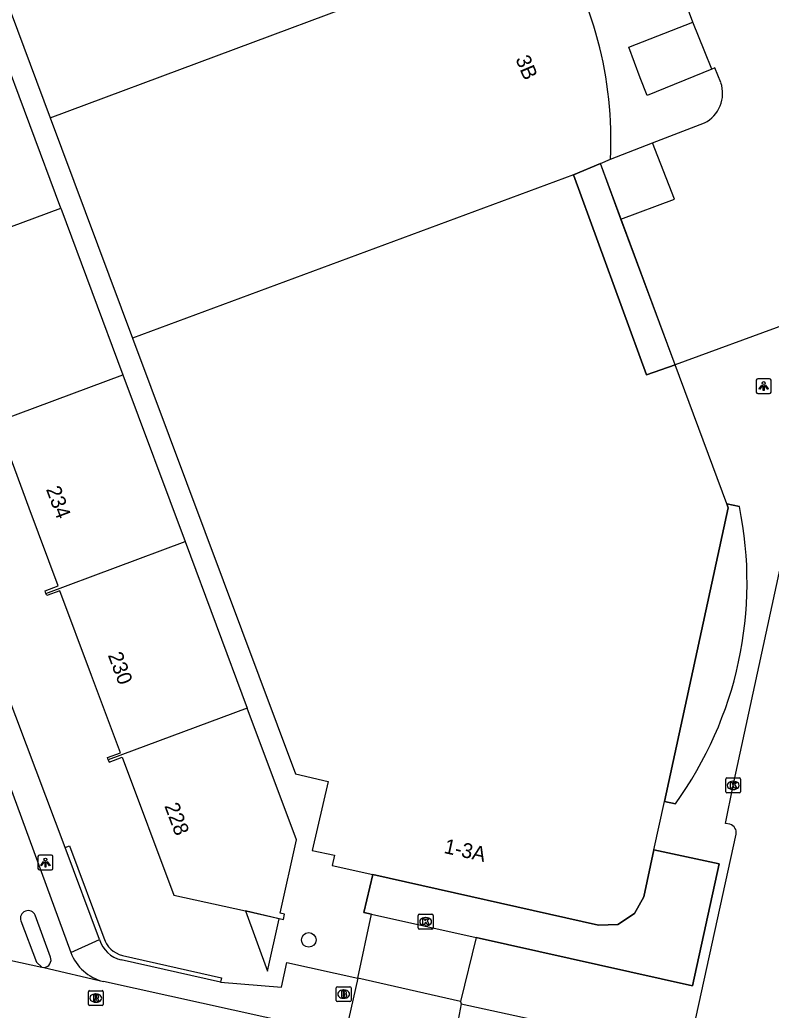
# Model space of a CAD drawing. Extents: x 162172 to 163187, y 382874 to 383684.
# Drawn here: x 162391 to 162441.7, y 383057.9 to 383124.7 of the extents above; entities that cross this region are included whole.
import ezdxf

# ---------------------------------------------------------------- set-up
doc = ezdxf.new("R2010")
doc.units = 0
for name, color, linetype in [('IMGEO_Boom', 7, 'Continuous'), ('IMGEO_Brandkraan', 7, 'Continuous'), ('IMGEO_Fietspad_open', 7, 'Continuous'), ('IMGEO_Kolk', 7, 'Continuous'), ('IMGEO_Lichtpunt', 7, 'Continuous'), ('IMGEO_Muur', 7, 'Continuous'), ('IMGEO_Pand', 7, 'Continuous'), ('IMGEO_Pand_nummerreeks', 7, 'Continuous'), ('IMGEO_Pand_overbouw', 7, 'Continuous'), ('IMGEO_Parkeervlak_open', 7, 'Continuous'), ('IMGEO_Rijbaan_lokaal_open', 7, 'Continuous'), ('IMGEO_Rioolput', 7, 'Continuous'), ('IMGEO_Voetpad_open', 7, 'Continuous')]:
    doc.layers.add(name, color=color, linetype=linetype)

msp = doc.modelspace()

# ---------------------------------------------------------------- linework, layer by layer
at = {"layer": 'IMGEO_Boom'}
msp.add_circle((162410.454, 383062.639), 0.489, dxfattribs=at)
at = {"layer": 'IMGEO_Brandkraan'}
for p, q in [((162412.308, 383058.552), (162412.308, 383059.404)), ((162412.383, 383059.478), (162413.235, 383059.478)), ((162412.796, 383059.258), (162412.821, 383059.258)), ((162413.309, 383059.404), (162413.309, 383058.552)), ((162413.235, 383058.478), (162412.383, 383058.478)), ((162412.819, 383058.698), (162412.794, 383058.698))]:
    msp.add_line(p, q, dxfattribs=at)
for points in [[(162412.308, 383058.552), (162412.308, 383059.404)], [(162412.383, 383059.478), (162413.235, 383059.478)], [(162412.656, 383059.178), (162412.656, 383058.778), (162412.869, 383058.778)], [(162412.887, 383059.178), (162412.656, 383059.178)], [(162412.835, 383059.097), (162412.781, 383059.097), (162412.781, 383059.021)], [(162412.781, 383059.021), (162412.834, 383059.021)], [(162412.843, 383058.945), (162412.781, 383058.945), (162412.781, 383058.864)], [(162413.309, 383059.404), (162413.309, 383058.552)], [(162413.235, 383058.478), (162412.383, 383058.478)], [(162412.781, 383058.864), (162412.843, 383058.864)]]:
    msp.add_lwpolyline(points, dxfattribs=at)
for centre, radius, start, end in [((162412.385, 383059.402), 0.0765, 91.55205, 178.44795), ((162412.385, 383059.402), 0.0765, 91.55205, 178.44795), ((162412.836, 383059.059), 0.0379, 267.82845, 90.93552), ((162412.844, 383058.904), 0.0404, 269.87594, 90.50774), ((162412.891, 383059.033), 0.145, 59.4692, 91.53667), ((162412.916, 383059.08), 0.0922, 285.51372, 58.15012), ((162412.921, 383058.888), 0.105, 301.31148, 78.98903), ((162413.233, 383059.402), 0.0765, 1.55205, 88.44795), ((162413.233, 383059.402), 0.0765, 1.55205, 88.44795), ((162412.385, 383058.554), 0.0765, 181.55205, 268.44795), ((162412.385, 383058.554), 0.0765, 181.55205, 268.44795), ((162412.875, 383059.029), 0.251, 268.66757, 293.53466), ((162413.233, 383058.554), 0.0765, 271.55205, 358.44795), ((162413.233, 383058.554), 0.0765, 271.55205, 358.44795)]:
    msp.add_arc(centre, radius, start, end, dxfattribs=at)
for centre, major_axis, ratio, start_param, end_param in [((162412.795, 383058.978), (-0.387, 0.002), 0.722429, 4.712389, 7.853982), ((162412.82, 383058.978), (-0.39, 0.002), 0.717154, 1.570796, 4.712389)]:
    msp.add_ellipse(centre, major_axis=major_axis, ratio=ratio, start_param=start_param, end_param=end_param, dxfattribs=at)
at = {"layer": 'IMGEO_Fietspad_open'}
for points in [[(162384.643, 383088.38), (162394.394, 383061.785)], [(162393.03, 383061.483), (162391.998, 383064.296)], [(162391.027, 383063.924), (162392.086, 383061.133), (162392.445, 383060.806)]]:
    msp.add_lwpolyline(points, dxfattribs=at)
for centre, radius, start, end in [((162391.518, 383064.094), 0.52, 22.80322, 199.12147), ((162397.377, 383062.933), 3.196, 201.04627, 255.89351), ((162392.553, 383061.291), 0.514, 272.97822, 21.92177)]:
    msp.add_arc(centre, radius, start, end, dxfattribs=at)
at = {"layer": 'IMGEO_Kolk'}
for p, q in [((162438.588, 383072.639), (162438.588, 383073.491)), ((162438.663, 383073.565), (162439.515, 383073.565)), ((162439.076, 383073.345), (162439.101, 383073.345)), ((162439.589, 383073.491), (162439.589, 383072.639)), ((162439.515, 383072.565), (162438.663, 383072.565)), ((162439.099, 383072.785), (162439.074, 383072.785)), ((162417.84, 383063.441), (162417.84, 383064.293)), ((162417.915, 383064.367), (162418.767, 383064.367)), ((162418.841, 383064.293), (162418.841, 383063.441)), ((162418.351, 383063.587), (162418.326, 383063.587)), ((162418.328, 383064.147), (162418.353, 383064.147)), ((162418.767, 383063.367), (162417.915, 383063.367))]:
    msp.add_line(p, q, dxfattribs=at)
for points in [[(162438.588, 383072.639), (162438.588, 383073.491)], [(162438.663, 383073.565), (162439.515, 383073.565)], [(162438.909, 383073.265), (162439.032, 383073.265), (162439.032, 383073.114), (162439.162, 383073.265), (162439.326, 383073.265), (162439.18, 383073.114), (162439.333, 383072.865), (162439.181, 383072.865), (162439.096, 383073.029), (162439.032, 383072.962), (162439.032, 383072.865), (162438.909, 383072.865), (162438.909, 383073.265)], [(162439.589, 383073.491), (162439.589, 383072.639)], [(162439.515, 383072.565), (162438.663, 383072.565)], [(162417.84, 383063.441), (162417.84, 383064.293)], [(162417.915, 383064.367), (162418.767, 383064.367)], [(162418.841, 383064.293), (162418.841, 383063.441)], [(162418.161, 383064.067), (162418.284, 383064.067), (162418.284, 383063.916), (162418.414, 383064.067), (162418.578, 383064.067), (162418.432, 383063.916), (162418.585, 383063.667), (162418.433, 383063.667), (162418.348, 383063.831), (162418.284, 383063.764), (162418.284, 383063.667), (162418.161, 383063.667), (162418.161, 383064.067)], [(162418.767, 383063.367), (162417.915, 383063.367)]]:
    msp.add_lwpolyline(points, dxfattribs=at)
for centre, start, end in [((162438.665, 383073.489), 91.55205, 178.44795), ((162438.665, 383073.489), 91.55205, 178.44795), ((162439.513, 383073.489), 1.55205, 88.44795), ((162439.513, 383073.489), 1.55205, 88.44795), ((162438.665, 383072.641), 181.55205, 268.44795), ((162438.665, 383072.641), 181.55205, 268.44795), ((162439.513, 383072.641), 271.55205, 358.44795), ((162439.513, 383072.641), 271.55205, 358.44795), ((162417.917, 383064.291), 91.55205, 178.44795), ((162417.917, 383064.291), 91.55205, 178.44795), ((162418.765, 383064.291), 1.55205, 88.44795), ((162418.765, 383064.291), 1.55205, 88.44795), ((162417.917, 383063.443), 181.55205, 268.44795), ((162417.917, 383063.443), 181.55205, 268.44795), ((162418.765, 383063.443), 271.55205, 358.44795), ((162418.765, 383063.443), 271.55205, 358.44795)]:
    msp.add_arc(centre, 0.0765, start, end, dxfattribs=at)
for centre, major_axis, ratio, start_param, end_param in [((162439.075, 383073.065), (-0.387, 0.002), 0.722429, 4.712389, 7.853982), ((162439.1, 383073.065), (-0.39, 0.002), 0.717154, 1.570796, 4.712389), ((162418.327, 383063.867), (-0.387, 0.002), 0.722429, 4.712389, 7.853982), ((162418.352, 383063.867), (-0.39, 0.002), 0.717154, 1.570796, 4.712389)]:
    msp.add_ellipse(centre, major_axis=major_axis, ratio=ratio, start_param=start_param, end_param=end_param, dxfattribs=at)
at = {"layer": 'IMGEO_Lichtpunt'}
for p, q in [((162440.647, 383100.407), (162440.647, 383099.6)), ((162440.647, 383100.407), (162440.647, 383099.6)), ((162441.549, 383100.502), (162440.741, 383100.502)), ((162441.549, 383100.502), (162440.741, 383100.502)), ((162441.643, 383099.6), (162441.643, 383100.407)), ((162441.643, 383099.6), (162441.643, 383100.407)), ((162440.741, 383099.506), (162441.549, 383099.506)), ((162440.741, 383099.506), (162441.549, 383099.506)), ((162393.088, 383068.356), (162392.28, 383068.356)), ((162393.088, 383068.356), (162392.28, 383068.356)), ((162392.186, 383068.261), (162392.186, 383067.454)), ((162392.186, 383068.261), (162392.186, 383067.454)), ((162393.182, 383067.454), (162393.182, 383068.261)), ((162393.182, 383067.454), (162393.182, 383068.261)), ((162392.28, 383067.36), (162393.088, 383067.36)), ((162392.28, 383067.36), (162393.088, 383067.36))]:
    msp.add_line(p, q, dxfattribs=at)
for points in [[(162441.021, 383100.071), (162441.06, 383100.043), (162440.872, 383099.781), (162440.834, 383099.808), (162441.021, 383100.071)], [(162441.123, 383100.023), (162441.17, 383100.023), (162441.17, 383099.701), (162441.123, 383099.701), (162441.123, 383100.023)], [(162441.233, 383100.043), (162441.271, 383100.07), (162441.458, 383099.808), (162441.419, 383099.78), (162441.233, 383100.043)], [(162392.56, 383067.925), (162392.599, 383067.897), (162392.411, 383067.635), (162392.373, 383067.662), (162392.56, 383067.925)], [(162392.662, 383067.877), (162392.709, 383067.877), (162392.709, 383067.555), (162392.662, 383067.555), (162392.662, 383067.877)], [(162392.772, 383067.897), (162392.81, 383067.924), (162392.997, 383067.662), (162392.958, 383067.634), (162392.772, 383067.897)]]:
    msp.add_lwpolyline(points, dxfattribs=at)
for centre in [(162441.146, 383100.205), (162392.685, 383068.059)]:
    msp.add_circle(centre, 0.0994, dxfattribs=at)
for centre, start, end in [((162440.741, 383100.407), 90, 180), ((162440.741, 383100.407), 90, 180), ((162441.549, 383100.407), 0, 90), ((162441.549, 383100.407), 0, 90), ((162440.741, 383099.6), 180, 270), ((162440.741, 383099.6), 180, 270), ((162441.549, 383099.6), 270, 0), ((162441.549, 383099.6), 270, 360), ((162392.28, 383068.261), 90, 180), ((162392.28, 383068.261), 90, 180), ((162393.088, 383068.261), 0, 90), ((162393.088, 383068.261), 0, 90), ((162392.28, 383067.454), 180, 270), ((162392.28, 383067.454), 180, 270), ((162393.088, 383067.454), 270, 0), ((162393.088, 383067.454), 270, 360)]:
    msp.add_arc(centre, 0.0946, start, end, dxfattribs=at)
at = {"layer": 'IMGEO_Muur'}
for points in [[(162394.027, 383068.875), (162394.311, 383068.989), (162396.634, 383062.777)], [(162396.342, 383062.654), (162394.027, 383068.875)], [(162397.882, 383061.595), (162404.565, 383060.086), (162404.504, 383059.784)], [(162404.504, 383059.784), (162397.792, 383061.287)]]:
    msp.add_lwpolyline(points, dxfattribs=at)
for centre, radius, start, end in [((162398.262, 383063.238), 2.006, 196.9096, 256.46575), ((162398.255, 383063.239), 1.686, 195.90207, 257.20953)]:
    msp.add_arc(centre, radius, start, end, dxfattribs=at)
at = {"layer": 'IMGEO_Pand'}
for points in [[(162386.314, 383136.041), (162393.012, 383118.114)], [(162393.012, 383118.114), (162426.675, 383130.669)], [(162393.719, 383112.013), (162389.521, 383123.265)], [(162393.012, 383118.114), (162398.566, 383103.245)], [(162430.126, 383115.031), (162430.805, 383115.318)], [(162428.312, 383114.263), (162430.126, 383115.031)], [(162428.312, 383114.263), (162398.566, 383103.245)], [(162435.169, 383101.446), (162433.233, 383100.756), (162428.312, 383114.263)], [(162384.329, 383108.518), (162393.719, 383112.013)], [(162393.719, 383112.013), (162397.917, 383100.761)], [(162398.566, 383103.245), (162409.551, 383073.841), (162411.755, 383073.321), (162410.679, 383068.677), (162412.18, 383068.364), (162412.033, 383067.661), (162414.788, 383067.044)], [(162438.655, 383092.052), (162435.169, 383101.446)], [(162388.531, 383097.267), (162397.917, 383100.761)], [(162397.917, 383100.761), (162402.115, 383089.508)], [(162392.725, 383086.013), (162392.664, 383086.186), (162393.551, 383086.518), (162391.588, 383091.776), (162389.467, 383097.455), (162388.591, 383097.113), (162388.531, 383097.267)], [(162434.449, 383071.975), (162438.754, 383091.786), (162438.655, 383092.052)], [(162392.725, 383086.013), (162402.115, 383089.508)], [(162402.115, 383089.508), (162406.303, 383078.283)], [(162396.931, 383074.787), (162396.875, 383074.943), (162397.745, 383075.269), (162395.801, 383080.477), (162393.664, 383086.2), (162392.777, 383085.868), (162392.725, 383086.013)], [(162406.303, 383078.283), (162396.931, 383074.787)], [(162396.931, 383074.787), (162396.987, 383074.631), (162397.871, 383074.962), (162401.36, 383065.647), (162406.181, 383064.588), (162408.744, 383064.011), (162408.825, 383064.372), (162408.535, 383064.448), (162409.619, 383069.394), (162406.303, 383078.283)], [(162433.739, 383068.707), (162434.449, 383071.975)], [(162414.788, 383067.044), (162429.999, 383063.636), (162431.314, 383063.684), (162432.431, 383064.409), (162433.054, 383065.554), (162433.739, 383068.707)]]:
    msp.add_lwpolyline(points, dxfattribs=at)
msp.add_arc((162405.226, 383116.667), 25.615, 356.98069, 33.13568, dxfattribs=at)
at = {"layer": 'IMGEO_Pand_overbouw'}
for points in [[(162428.312, 383114.263), (162433.233, 383100.756), (162435.169, 383101.446), (162430.126, 383115.031)], [(162438.136, 383067.771), (162433.739, 383068.707), (162433.054, 383065.554), (162432.431, 383064.409), (162431.314, 383063.684), (162429.999, 383063.636), (162414.788, 383067.044), (162414.165, 383064.487), (162414.69, 383064.37), (162421.74, 383062.801), (162436.343, 383059.549)], [(162408.451, 383064.069), (162406.181, 383064.588), (162407.675, 383060.527)]]:
    msp.add_lwpolyline(points, close=True, dxfattribs=at)
msp.add_lwpolyline([(162439.511, 383091.872), (162438.655, 383092.052), (162438.754, 383091.786), (162434.449, 383071.975), (162435.198, 383071.827)], dxfattribs=at)
msp.add_arc((162414.47, 383086.774), 25.555, 324.20571, 11.50836, dxfattribs=at)
at = {"layer": 'IMGEO_Parkeervlak_open'}
msp.add_lwpolyline([(162413.755, 383060.066), (162414.69, 383064.37)], dxfattribs=at)
at = {"layer": 'IMGEO_Rijbaan_lokaal_open'}
for points in [[(162436.377, 383124.551), (162435.65, 383126.509)], [(162437.65, 383121.39), (162437.179, 383122.56), (162436.377, 383124.551)], [(162438.257, 383120.477), (162437.851, 383121.472), (162437.65, 383121.39)], [(162433.654, 383116.416), (162437.147, 383117.761)], [(162430.805, 383115.318), (162433.654, 383116.416)], [(162431.52, 383111.275), (162435.119, 383112.615), (162433.654, 383116.416)], [(162431.52, 383111.275), (162430.126, 383115.031)], [(162435.169, 383101.446), (162431.52, 383111.275)], [(162442.66, 383104.175), (162435.169, 383101.446)], [(162438.868, 383070.439), (162438.579, 383070.494), (162439.089, 383073.065), (162445.304, 383101.713)], [(162436.061, 383054.999), (162439.287, 383069.766)], [(162389.018, 383061.534), (162392.445, 383060.806)], [(162392.445, 383060.806), (162392.58, 383060.778)], [(162392.58, 383060.778), (162396.598, 383059.833)], [(162411.956, 383056.427), (162396.598, 383059.833)], [(162413.755, 383060.066), (162413.141, 383057.26)], [(162420.694, 383058.49), (162413.755, 383060.066)], [(162420.746, 383058.322), (162420.537, 383057.245)], [(162420.694, 383058.49), (162420.746, 383058.322)]]:
    msp.add_lwpolyline(points, dxfattribs=at)
for centre, radius, start, end in [((162436.15, 383119.753), 2.228, 296.5884, 18.95298), ((162438.716, 383069.878), 0.581, 348.91981, 74.89178)]:
    msp.add_arc(centre, radius, start, end, dxfattribs=at)
at = {"layer": 'IMGEO_Rioolput'}
for p, q in [((162395.586, 383058.286), (162395.586, 383059.138)), ((162395.661, 383059.212), (162396.513, 383059.212)), ((162396.074, 383058.992), (162396.099, 383058.992)), ((162396.587, 383059.138), (162396.587, 383058.286)), ((162396.097, 383058.432), (162396.072, 383058.432)), ((162396.513, 383058.212), (162395.661, 383058.212))]:
    msp.add_line(p, q, dxfattribs=at)
for points in [[(162395.586, 383058.286), (162395.586, 383059.138)], [(162395.661, 383059.212), (162396.513, 383059.212)], [(162396.175, 383058.91), (162395.923, 383058.912), (162395.923, 383058.512)], [(162396.587, 383059.138), (162396.587, 383058.286)], [(162395.923, 383058.512), (162396.047, 383058.512), (162396.047, 383058.674), (162396.058, 383058.674)], [(162396.101, 383058.831), (162396.047, 383058.831), (162396.047, 383058.75)], [(162396.047, 383058.75), (162396.099, 383058.75)], [(162396.105, 383058.645), (162396.176, 383058.512), (162396.316, 383058.512), (162396.251, 383058.638)], [(162396.513, 383058.212), (162395.661, 383058.212)]]:
    msp.add_lwpolyline(points, dxfattribs=at)
for centre, radius, start, end in [((162395.663, 383059.136), 0.0765, 91.55205, 178.44795), ((162395.663, 383059.136), 0.0765, 91.55205, 178.44795), ((162396.174, 383058.8), 0.109, 350.36119, 89.41601), ((162396.511, 383059.136), 0.0765, 1.55205, 88.44795), ((162396.511, 383059.136), 0.0765, 1.55205, 88.44795), ((162395.663, 383058.288), 0.0765, 181.55205, 268.44795), ((162395.663, 383058.288), 0.0765, 181.55205, 268.44795), ((162396.057, 383058.621), 0.0533, 26.02933, 88.69889), ((162396.083, 383058.939), 0.19, 274.7715, 282.96867), ((162396.107, 383058.735), 0.0964, 77.00612, 93.18647), ((162396.121, 383058.792), 0.0378, 276.66336, 79.67722), ((162396.172, 383058.8), 0.112, 277.58423, 350.98172), ((162396.156, 383058.585), 0.108, 29.51342, 73.79051), ((162396.511, 383058.288), 0.0765, 271.55205, 358.44795), ((162396.511, 383058.288), 0.0765, 271.55205, 358.44795)]:
    msp.add_arc(centre, radius, start, end, dxfattribs=at)
for centre, major_axis, ratio, start_param, end_param in [((162396.073, 383058.712), (-0.387, 0.002), 0.722429, 4.712389, 7.853982), ((162396.098, 383058.712), (-0.39, 0.002), 0.717154, 1.570796, 4.712389)]:
    msp.add_ellipse(centre, major_axis=major_axis, ratio=ratio, start_param=start_param, end_param=end_param, dxfattribs=at)
at = {"layer": 'IMGEO_Voetpad_open'}
for points in [[(162394.027, 383068.875), (162388.064, 383084.639), (162358.858, 383162.93), (162351.468, 383182.584)], [(162437.65, 383121.39), (162433.276, 383119.603), (162432.814, 383120.802), (162432.047, 383122.88), (162436.377, 383124.551)], [(162438.655, 383092.052), (162439.511, 383091.872)], [(162435.198, 383071.827), (162434.449, 383071.975)], [(162433.739, 383068.707), (162438.136, 383067.771), (162436.343, 383059.549), (162421.74, 383062.801)], [(162414.69, 383064.37), (162414.165, 383064.487), (162414.788, 383067.044)], [(162414.69, 383064.37), (162421.74, 383062.801)], [(162394.394, 383061.785), (162396.342, 383062.654)], [(162421.74, 383062.801), (162420.694, 383058.49)], [(162404.504, 383059.784), (162408.62, 383059.445), (162408.973, 383061.102), (162413.755, 383060.066)], [(162420.746, 383058.322), (162436.061, 383054.999)]]:
    msp.add_lwpolyline(points, dxfattribs=at)
msp.add_arc((162414.47, 383086.774), 25.555, 324.20571, 11.50836, dxfattribs=at)

# ---------------------------------------------------------------- texts
at = {"layer": 'IMGEO_Pand_nummerreeks'}
for s, rotation, p in [('3B', 292.93735, (162424.383, 383122.074)), ('234', 290.47157, (162392.714, 383093.047)), ('230', 290.47157, (162396.887, 383081.855)), ('228', 290.5346, (162400.701, 383071.681)), ('1-3A', 347.52489, (162419.52, 383068.509))]:
    msp.add_text(s, height=1, rotation=rotation, dxfattribs=at).set_placement(p)

doc.saveas('drawing.dxf')
